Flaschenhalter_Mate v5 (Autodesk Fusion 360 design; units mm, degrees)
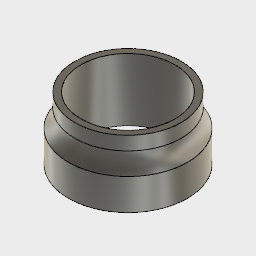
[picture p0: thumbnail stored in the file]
sketch "Skizze1" plane through (0, 0, 0) normal (1, 0, 0) x axis (0, 1, 0)
sketch "Skizze2"
  circle C1 centre (0, 0) radius 47.5
  dimension "d1" diameter C1 = 95 (= "75 mm + 20 mm")
extrude "Extrusion1" new body sketch "Skizze2" blind 25
sketch "Skizze3" plane through (0, 0, 25) normal (0, 0, 1) x axis (-1, 0, 0)
  circle C1 centre (0, 0) radius 47.5
  circle C2 centre (0, 0) radius 42.5
  dimension "d4" diameter C2 = 85 (= "75 mm + 10 mm")
extrude "Extrusion2" add sketch "Skizze3" profile of C2 along normal blind 25
sketch "Skizze4" plane through (0, 0, 50) normal (0, 0, 1) x axis (-1, 0, 0)
  circle C1 centre (0, 0) radius 42.5
  circle C2 centre (0, 0) radius 37.5
  dimension "d7" diameter C2 = 75
extrude "Extrusion3" cut sketch "Skizze4" profile of C2 against normal blind 50
fillet "Abrundung" radius 22.5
